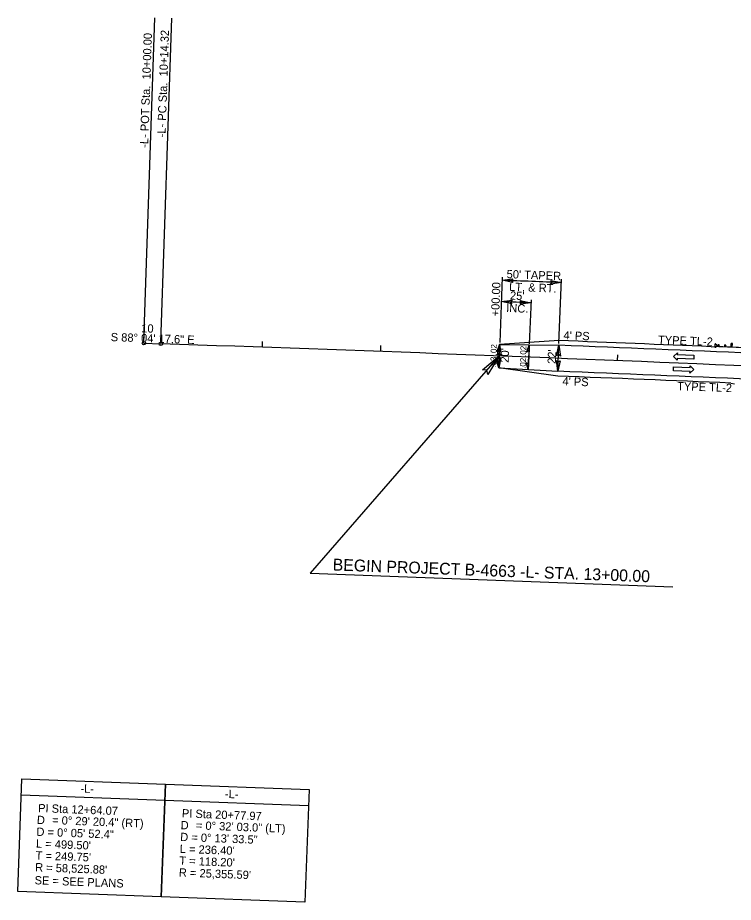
# Model space of a CAD drawing. Extents: x 2170295 to 2171718, y 723585 to 724580.
# Drawn here: x 2170295 to 2170899, y 723622 to 724369 of the extents above; entities that cross this region are included whole.
import ezdxf

# ---------------------------------------------------------------- set-up
doc = ezdxf.new("R2010")
doc.units = 0
for name, color, linetype in [('Prop Dimension', 7, 'Continuous'), ('Prop DSN Text', 7, 'Continuous'), ('Prop EOT', 7, 'Continuous'), ('Prop Grid Mask', 7, 'Continuous'), ('Prop Guardrail Anchor Unit CELL', 7, 'Continuous'), ('Prop Horizontal Alignment', 7, 'Continuous'), ('Prop Horizontal Alignment Curve and Spiral Data', 7, 'Continuous'), ('Prop Horizontal Alignment Direction Label', 7, 'Continuous'), ('Prop Horizontal Alignment Station Label', 7, 'Continuous'), ('Prop Horizontal Alignment Tick Label', 7, 'Continuous'), ('Prop Horizontal Alignment Tick Large', 7, 'Continuous'), ('Prop Horizontal Alignment Tick Small', 7, 'Continuous'), ('Prop Lane Arrow CELL', 7, 'Continuous'), ('Prop Paved Shoulder', 7, 'Continuous'), ('Prop Superelevation  Arrow CELL', 7, 'Continuous'), ('Prop Superelevation Label', 7, 'Continuous'), ('Prop Terminator CELL', 7, 'Continuous')]:
    doc.layers.add(name, color=color, linetype=linetype)

msp = doc.modelspace()

# ---------------------------------------------------------------- linework, layer by layer
at = {"layer": 'Prop Dimension'}
for p, q in [((2170703.53, 724149.91), (2170701.41, 724094.87)), ((2170751.42, 724093.92), (2170753.56, 724148.19)), ((2170727.84, 724130.93), (2170726.39, 724093.77)), ((2170701.35, 724093.27), (2170700.58, 724073.31)), ((2170750.5, 724070.5), (2170751.36, 724092.48)), ((2170700.97, 724083.44), (2170541.33, 723900.02)), ((2170541.33, 723900.02), (2170847.5, 723888.56))]:
    msp.add_line(p, q, dxfattribs=at)
for radius, start in [(58589.86, 87.7429222), (58571.8, 87.7673968)]:
    msp.add_arc((2168445.99, 665601.01), radius, start, 87.7918713, dxfattribs=at)
at = {"layer": 'Prop EOT'}
for p, q in [((2170701.35, 724093.27), (2170751.36, 724092.48)), ((2170700.58, 724073.31), (2170750.5, 724070.5))]:
    msp.add_line(p, q, dxfattribs=at)
for radius in [58536.88, 58514.88]:
    msp.add_arc((2168445.99, 665601.01), radius, 87.5825428, 87.7429222, dxfattribs=at)
at = {"layer": 'Prop Grid Mask'}
for p, q in [((2170297.68, 723713), (2170418.83, 723708.47)), ((2170418.83, 723708.47), (2170539.98, 723703.93))]:
    msp.add_line(p, q, dxfattribs=at)
for points in [[(2170298.18, 723726.39), (2170419.33, 723721.86), (2170415.77, 723626.72), (2170294.62, 723631.25)], [(2170419.33, 723721.86), (2170540.48, 723717.33), (2170536.92, 723622.19), (2170415.77, 723626.72)]]:
    msp.add_lwpolyline(points, close=True, dxfattribs=at)
at = {"layer": 'Prop Guardrail Anchor Unit CELL'}
for p, q in [((2170883.17, 724090.72), (2170883.29, 724093.66)), ((2170883.56, 724093.65), (2170883.29, 724093.66)), ((2170884.51, 724091.52), (2170883.44, 724090.71)), ((2170883.56, 724093.65), (2170884.56, 724092.75)), ((2170884.56, 724092.75), (2170884.51, 724091.52)), ((2170885.8, 724091.47), (2170884.51, 724091.52)), ((2170884.54, 724092.24), (2170885.83, 724092.18)), ((2170885.8, 724091.46), (2170885.86, 724092.97)), ((2170886.74, 724092.94), (2170885.8, 724091.46)), ((2170886.67, 724091.42), (2170885.8, 724091.46)), ((2170886.74, 724092.94), (2170885.86, 724092.97)), ((2170886.67, 724091.42), (2170885.86, 724092.97)), ((2170886.24, 724091.44), (2170908.18, 724090.51)), ((2170886.67, 724091.42), (2170886.74, 724092.94)), ((2170891.28, 724091.22), (2170891.35, 724092.74)), ((2170892.22, 724092.7), (2170891.28, 724091.22)), ((2170892.16, 724091.19), (2170891.28, 724091.22)), ((2170892.23, 724092.7), (2170891.35, 724092.74)), ((2170892.16, 724091.19), (2170891.35, 724092.74)), ((2170892.16, 724091.19), (2170892.23, 724092.7)), ((2170896.77, 724090.99), (2170896.9, 724094.02)), ((2170897.71, 724092.47), (2170896.77, 724090.99)), ((2170896.83, 724092.51), (2170897.78, 724093.99)), ((2170897.71, 724092.47), (2170896.83, 724092.51)), ((2170897.65, 724090.95), (2170896.83, 724092.51)), ((2170897.78, 724093.99), (2170896.9, 724094.02)), ((2170896.9, 724094.02), (2170897.71, 724092.47)), ((2170897.65, 724090.95), (2170897.78, 724093.99)), ((2170883.44, 724090.71), (2170883.17, 724090.72)), ((2170897.65, 724090.95), (2170896.77, 724090.99))]:
    msp.add_line(p, q, dxfattribs=at)
at = {"layer": 'Prop Horizontal Alignment'}
msp.add_line((2170401.16, 724094.23), (2170415.48, 724093.75), dxfattribs=at)
msp.add_arc((2168445.99, 665601.01), 58525.88, 87.5825428, 88.0715445, dxfattribs=at)
at = {"layer": 'Prop Horizontal Alignment Station Label'}
for p, q in [((2170401.21, 724095.73), (2170410.42, 724369.07)), ((2170415.53, 724095.25), (2170424.73, 724368.59))]:
    msp.add_line(p, q, dxfattribs=at)
for centre in [(2170401.16, 724094.23), (2170415.48, 724093.75)]:
    msp.add_circle(centre, 1.5, dxfattribs=at)
at = {"layer": 'Prop Horizontal Alignment Tick Large'}
msp.add_line((2170401.16, 724094.23), (2170401.43, 724102.22), dxfattribs=at)
at = {"layer": 'Prop Horizontal Alignment Tick Small'}
for p, q in [((2170501.11, 724090.8), (2170501.28, 724095.8)), ((2170601.04, 724087.2), (2170601.22, 724092.2)), ((2170700.97, 724083.44), (2170701.16, 724088.43)), ((2170800.89, 724079.5), (2170801.09, 724084.49))]:
    msp.add_line(p, q, dxfattribs=at)
at = {"layer": 'Prop Lane Arrow CELL'}
for p, q in [((2170848.06, 724083.11), (2170851.34, 724086.18)), ((2170851.34, 724086.18), (2170851.27, 724084.68)), ((2170851.27, 724084.68), (2170865.26, 724084.11)), ((2170865.26, 724084.11), (2170865.13, 724080.81)), ((2170851.08, 724079.89), (2170848.06, 724083.11)), ((2170851.14, 724081.39), (2170851.08, 724079.89)), ((2170865.13, 724080.81), (2170851.14, 724081.39)), ((2170848.04, 724070.91), (2170848.18, 724074.21)), ((2170862.03, 724070.33), (2170848.04, 724070.91)), ((2170848.18, 724074.21), (2170862.17, 724073.63)), ((2170865.25, 724071.9), (2170861.97, 724068.84)), ((2170861.97, 724068.84), (2170862.03, 724070.33)), ((2170862.17, 724073.63), (2170862.23, 724075.13)), ((2170862.23, 724075.13), (2170865.25, 724071.9))]:
    msp.add_line(p, q, dxfattribs=at)
at = {"layer": 'Prop Paved Shoulder'}
for p, q in [((2170751.52, 724096.48), (2170701.35, 724093.27)), ((2170751.52, 724096.48), (2170751.52, 724096.48)), ((2170879.86, 724091.28), (2170883.2, 724091.56)), ((2170919.32, 724090.04), (2170883.2, 724091.56)), ((2170750.34, 724066.5), (2170700.58, 724073.31)), ((2170896.38, 724060.56), (2170899.69, 724060.01))]:
    msp.add_line(p, q, dxfattribs=at)
for radius, start in [(58540.88, 87.6172158), (58510.88, 87.5998016)]:
    msp.add_arc((2168445.99, 665601.01), radius, start, 87.7429222, dxfattribs=at)
at = {"layer": 'Prop Superelevation  Arrow CELL'}
for p, q in [((2170701.35, 724093.27), (2170700.89, 724081.28)), ((2170726.36, 724092.87), (2170725.89, 724080.88)), ((2170700.58, 724073.31), (2170701.04, 724085.3)), ((2170725.54, 724071.9), (2170726.01, 724083.89))]:
    msp.add_line(p, q, dxfattribs=at)
for points in [[(2170701.35, 724093.27), (2170699.12, 724087.35), (2170701.17, 724088.65)], [(2170726.36, 724092.87), (2170724.12, 724086.96), (2170726.18, 724088.25)], [(2170700.58, 724073.31), (2170698.81, 724079.38), (2170700.76, 724077.93)], [(2170725.54, 724071.9), (2170723.77, 724077.98), (2170725.72, 724076.52)]]:
    msp.add_lwpolyline(points, close=True, dxfattribs=at)
at = {"layer": 'Prop Superelevation Label'}
for p, q in [((2170701.35, 724093.27), (2170700.58, 724073.31)), ((2170726.36, 724092.87), (2170725.54, 724071.9))]:
    msp.add_line(p, q, dxfattribs=at)
at = {"layer": 'Prop Terminator CELL'}
for points in [[(2170712.37, 724145.47), (2170703.43, 724147.37), (2170712.54, 724148.62), (2170711.33, 724147.06)], [(2170744.52, 724147.32), (2170753.45, 724145.42), (2170744.35, 724144.18), (2170745.56, 724145.73)], [(2170711.67, 724127.42), (2170702.74, 724129.32), (2170711.84, 724130.57), (2170710.63, 724129.02)], [(2170718.81, 724130.25), (2170727.74, 724128.35), (2170718.63, 724127.1), (2170719.85, 724128.66)], [(2170699.45, 724084.33), (2170701.35, 724093.27), (2170702.6, 724084.16), (2170701.04, 724085.37)], [(2170749.46, 724083.55), (2170751.36, 724092.48), (2170752.61, 724083.37), (2170751.05, 724084.59)], [(2170686.81, 724071.89), (2170700.97, 724083.44), (2170691.5, 724067.68), (2170690.6, 724071.52)], [(2170702.47, 724082.24), (2170700.58, 724073.31), (2170699.33, 724082.41), (2170700.88, 724081.2)], [(2170752.4, 724079.43), (2170750.5, 724070.5), (2170749.26, 724079.6), (2170750.81, 724078.39)]]:
    msp.add_lwpolyline(points, close=True, dxfattribs=at)

# ---------------------------------------------------------------- texts
at = {"layer": 'Prop DSN Text'}
for s, height, rotation, p in [("50' TAPER", 7, 357.7674, (2170707.13, 724149.22)), ('+00.00', 7, 87.7674, (2170700.97, 724116.78)), ('LT. & RT.', 7, 357.7674, (2170709.25, 724138.53)), ("25'", 7, 357.7674, (2170709.98, 724131.08)), ('INC.', 7, 357.7674, (2170706.79, 724120.62)), ("4' PS", 7, 357.69757, (2170755.12, 724097.53)), ('TYPE TL-2', 7, 357.85741, (2170834.91, 724093.73)), ("20'", 7, 87.79187, (2170708.96, 724077.69)), ("22'", 7, 87.74292, (2170748.72, 724076.63)), ("4' PS", 7, 357.69757, (2170754.23, 724058.75)), ('TYPE TL-2', 7, 357.85741, (2170851.02, 724054.62)), ('BEGIN PROJECT B-4663 -L- STA. 13+00.00', 10, 357.8574, (2170560.33, 723902.41))]:
    msp.add_text(s, height=height, rotation=rotation, dxfattribs=at).set_placement(p)
at = {"layer": 'Prop Horizontal Alignment Curve and Spiral Data'}
for s, p in [('-L-', (2170347.42, 723714.89)), ('-L-', (2170469.42, 723710.32)), ('PI Sta 12+64.07', (2170311.74, 723698.34)), ('D', (2170310.7, 723688.37)), ('PI Sta 20+77.97', (2170433.09, 723693.92)), ('= 0%%d 29\' 20.4" (RT)', (2170323.55, 723688.18)), ('D', (2170432.04, 723683.95)), ('= 0%%d 32\' 03.0" (LT)', (2170444.89, 723683.77)), ('D = 0%%d 05\' 52.4"', (2170310.32, 723678.38)), ('D = 0%%d 13\' 33.5"', (2170431.67, 723673.96)), ("L = 499.50'", (2170309.95, 723668.38)), ("L = 236.40'", (2170431.29, 723663.97)), ("T = 249.75'", (2170309.57, 723658.39)), ("T = 118.20'", (2170430.92, 723653.98)), ("R = 58,525.88'", (2170309.2, 723648.4)), ("R = 25,355.59'", (2170430.54, 723643.98)), ('SE = SEE PLANS', (2170308.79, 723637.41))]:
    msp.add_text(s, height=7, rotation=357.85741, dxfattribs=at).set_placement(p)
at = {"layer": 'Prop Horizontal Alignment Direction Label'}
msp.add_text('S 88%%d 04\' 17.6" E', height=7, rotation=358.07154, dxfattribs=at).set_placement((2170373.04, 724096.02))
at = {"layer": 'Prop Horizontal Alignment Station Label'}
for s, p in [('-L- POT Sta.  10+00.00', (2170404.71, 724259.1)), ('-L- PC Sta.  10+14.32', (2170419.34, 724267.93))]:
    msp.add_text(s, height=7, rotation=88.07154, dxfattribs=at).set_placement(p)
at = {"layer": 'Prop Horizontal Alignment Tick Label'}
msp.add_text('10', height=7, rotation=358.07154, dxfattribs=at).set_placement((2170398.8, 724103.43))
at = {"layer": 'Prop Superelevation Label'}
for s, rotation, p in [('.02', 87.79187, (2170698.7, 724083.99)), ('.02', 87.7674, (2170723.66, 724082.64)), ('.03', 87.79187, (2170698.35, 724073.55)), ('.02', 87.7674, (2170723.34, 724072.54))]:
    msp.add_text(s, height=5, rotation=rotation, dxfattribs=at).set_placement(p)

doc.saveas('drawing.dxf')
